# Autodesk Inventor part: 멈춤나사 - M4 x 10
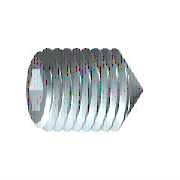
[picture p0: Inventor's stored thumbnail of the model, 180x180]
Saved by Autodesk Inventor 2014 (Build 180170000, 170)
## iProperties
Created: 2012-02
Part Number: 멈춤나사 - M4 x 10
Material: 강철, 연강
Description: 6각 소켓 머리 없는 멈춤 나사
Document SubType Name: Modeling
Standard: KS B 1028
Designer: mduedu
Standards Organization: KS
Language: ko-KR
Size Designation: 원추점 M4x10
Categories: <MemberInstance><Categories><Category DisplayName="조임쇠" InternalName="e4da775c-781d-43d5-af7c-5136215cf5a6" Mnemonic="FSTN"><Category DisplayName="볼트" InternalN
Density: 7.86 g/cm^3
Mass: 0.792069 g
Surface Area: 1.48192 cm^2
Volume: 0.100772 cm^3
Appearance: 강철
Author: mduedu
IsCustomPart: 1
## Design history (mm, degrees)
sketch "스케치1"
  geometry: L1 (0, 0)-(6.833, 0); L2 (10, 1.155)-(10, 2); L3 (10, 2)-(0, 2); L4 (10, 1.155)-(7.5, 1.155); L5 (7.5, 1.155)-(6.833, 0); L6 (0, -0.4)-(0, 2.4) reference; L7 (0, 2)-(0, 0)
  constraints: 13 end point, 3 parallel, 1 collinear, 1 perpendicular, 1 point on line
  dimensions: "d0" = 2.5 distance of L2.start L4.end (= INTI); "d1" = 60 deg angle of L5 L1; "d2" = 4 diameter of L3 L1 (= NND); "d3" = 2.3094 diameter of L4 L1 (= 1.1547 x SW); "d5" = 10 distance from line of L2 L3.end (= NLG)
revolve "본체" sketch "스케치1" stored, may be unused: angle "d6" = 90 deg
sketch "스케치2"
  geometry: L1 (-0.577, 1)-(0.577, 1); L2 (0.577, 1)-(1.155, 0); L3 (1.155, 0)-(0.577, -1); L4 (0.577, -1)-(-0.577, -1); L5 (-0.577, -1)-(-1.155, 0); L6 (-1.155, 0)-(-0.577, 1); 3 further points
  constraints: 12 end point, 1 coincident, 1 horizontal, 13 other
extrude "슬롯" join sketch "스케치2" taper "d7" = 0 deg; stored distance "d21" = 10
workaxis "Work Axis1"
workplane "Work Plane1"
sketch "스케치4"
  geometry: L1 (-5, 0.2)-(-3.2, 2) reference; L2 (-5, -0.2)-(-3.2, -2) reference; L3 (-3.2, 2)-(-5.2, 0); L4 (-3.2, -2)-(-5.2, 0); 2 further points
  constraints: 4 end point, 2 collinear, 1 coincident
body "Solid1"
feature "스레드" dims "d12" = 10 (= NLG), "d13" = 0
chamfer "모따기1" distance "d8" = 1.8 (computed from NND, SPD, FAWI); stored, may be unused: angle "d9" = 45 deg (= FAWI), second distance "d34" = 1.8 (computed from NND, SPD, FAWI)
chamfer "모따기2" distance "d10" = 0.42941 (= -0.5 x GD1 + 0.5 x NND); stored, may be unused: angle "d11" = 45 deg (= FAWI), second distance "d35" = 0.42941 (= -0.5 x GD1 + 0.5 x NND)
other parameters: "NND" = 4 [user parameter; used in 5 equation terms], "NLG" = 10 [user parameter; used in 2 equation terms], "INTI" = 2.5 [user parameter; used in 1 equation term], "FAWI" = 45 deg [user parameter; used in 4 equation terms], "SW" = 2 [user parameter; used in 2 equation terms], "GD1" = 3.14117 (= THREADDIA - 1.2269 x PTC) [user parameter; used in 2 equation terms], "d4" = 0, "FAWI1" = 45 deg [user parameter], "SPD" = 0.4 [user parameter; used in 2 equation terms], "d36" = 0, "d37" = 0, "GUL" = 0.42941 (= 0.61345 x PTC) [user parameter], "TPU" = 14.28571 (computed from PTC) [user parameter], "TOA" = 30 deg [user parameter], "THREADDIA" = 4 [user parameter; used in 1 equation term], "PTC" = 0.7 [user parameter; used in 4 equation terms], "GAL" = 0.42941 (= 0.61345 x PTC) [user parameter], "E0" = 2.31 (= 1.155 x SW) [user parameter]
